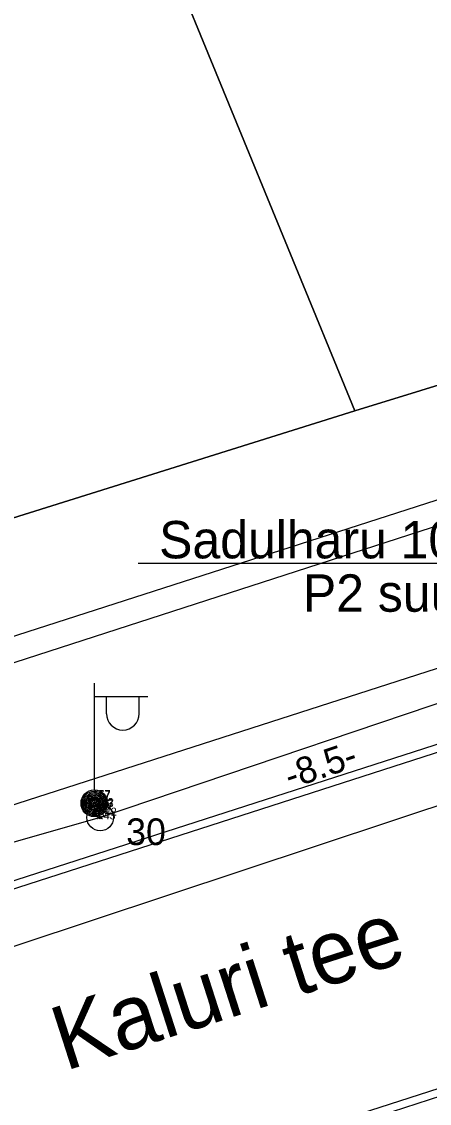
# Model space of a CAD drawing. Extents: x 546339 to 546593, y 6597108 to 6597251.
# Drawn here: x 546460.54 to 546468.19, y 6597179 to 6597199.27 of the extents above; entities that cross this region are included whole.
import ezdxf

# ---------------------------------------------------------------- set-up
doc = ezdxf.new("R2010")
doc.units = 0
for name, color, linetype in [('HOONE', 7, 'Continuous'), ('JOONSIDE', 7, 'Continuous'), ('KOORDPUNKT', 7, 'Continuous'), ('MOOTKORG-EH2000', 7, 'Continuous'), ('MOOTMPUNKT', 7, 'Continuous'), ('MOOTNR', 7, 'Continuous'), ('MOOTPIIR', 7, 'Continuous'), ('PIIR', 7, 'Continuous'), ('POST', 7, 'Continuous'), ('SITRASS', 7, 'Continuous'), ('TEE', 7, 'Continuous')]:
    doc.layers.add(name, color=color, linetype=linetype)

msp = doc.modelspace()

# ---------------------------------------------------------------- linework, layer by layer
at = {"layer": 'HOONE'}
for points in [[(546461.888, 6597184.636), (546461.9, 6597184.561)], [(546461.916, 6597184.6), (546461.899, 6597184.649)]]:
    msp.add_lwpolyline(points, dxfattribs=at)
at = {"layer": 'KOORDPUNKT'}
for radius in [0.25, 0.025, 0.0221, 0.0191, 0.0161, 0.0132, 0.0102, 0.00726, 0.0043]:
    msp.add_circle((546462.018, 6597184.359), radius, dxfattribs=at)
at = {"layer": 'MOOTMPUNKT'}
for centre in [(546461.875, 6597184.723), (546461.879, 6597184.706), (546461.913, 6597184.474), (546461.936, 6597184.543)]:
    msp.add_circle(centre, 0.03, dxfattribs=at)
at = {"layer": 'MOOTPIIR'}
for points in [[(546431.038, 6597182.742), (546435.363, 6597179.169), (546476.861, 6597192.584), (546477.551, 6597196.157), (546480.466, 6597197.411), (546483.506, 6597194.527), (546510.21, 6597203.146)], [(546510.398, 6597198.602), (546490.433, 6597192.051), (546491.122, 6597184.372), (546487.988, 6597183.494), (546485.449, 6597190.17), (546474.636, 6597186.911), (546476.297, 6597179.326), (546473.131, 6597178.291), (546470.279, 6597185.218), (546447.869, 6597177.79), (546448.872, 6597171.02), (546446.584, 6597170.142), (546443.888, 6597176.348), (546374.62, 6597155.63)]]:
    msp.add_lwpolyline(points, dxfattribs=at)
at = {"layer": 'PIIR'}
for points in [[(546459.55, 6597209.598), (546466.79, 6597191.98), (546491.04, 6597199.45), (546483.698, 6597217.73)], [(546424.887, 6597197.926), (546431.99, 6597181.07), (546466.79, 6597191.98), (546459.55, 6597209.598)], [(546510.07, 6597205.36), (546491.04, 6597199.45), (546466.79, 6597191.98), (546431.99, 6597181.07), (546399.93, 6597171.7), (546399.49, 6597172.55), (546362.07, 6597160.42), (546350.54, 6597167.22), (546341.457, 6597167.537)]]:
    msp.add_lwpolyline(points, dxfattribs=at)
at = {"layer": 'POST'}
for p, q in [((546461.907, 6597184.875), (546461.907, 6597186.875)), ((546461.907, 6597186.625), (546462.907, 6597186.625)), ((546462.134, 6597186.304), (546462.134, 6597186.625)), ((546462.747, 6597186.304), (546462.747, 6597186.625)), ((546461.907, 6597184.625), (546461.907, 6597184.625))]:
    msp.add_line(p, q, dxfattribs=at)
for radius in [0.25, 0.225, 0.2, 0.175, 0.15, 0.125, 0.1, 0.075, 0.05, 0.025]:
    msp.add_circle((546461.907, 6597184.625), radius, dxfattribs=at)
msp.add_arc((546462.441, 6597186.304), 0.306, 180, 0, dxfattribs=at)
at = {"layer": 'SITRASS'}
for points in [[(546472.601, 6597187.97), (546470.63, 6597189.117), (546462.729, 6597189.117)], [(546472.601, 6597187.97), (546470.118, 6597187.092), (546462.018, 6597184.359), (546455.281, 6597182.437), (546447.986, 6597180.224), (546445.217, 6597179.513)]]:
    msp.add_lwpolyline(points, dxfattribs=at)
at = {"layer": 'TEE'}
for p, q in [((546518.272, 6597195.197), (546396.577, 6597156.011)), ((546439.027, 6597176.299), (546484.965, 6597191.091)), ((546484.87, 6597190.902), (546439.237, 6597176.208))]:
    msp.add_line(p, q, dxfattribs=at)
for points in [[(546514.456, 6597205.157), (546396.804, 6597167.285), (546396.804, 6597167.285)], [(546515.375, 6597202.301), (546397.724, 6597164.429), (546397.724, 6597164.429)], [(546396.531, 6597156.154), (546518.226, 6597195.34), (546518.226, 6597195.34)]]:
    msp.add_lwpolyline(points, dxfattribs=at)

# ---------------------------------------------------------------- texts
at = {"layer": 'JOONSIDE'}
msp.add_text('-8.5-', height=0.5, rotation=18.6456, dxfattribs=at).set_placement((546465.572, 6597184.887))
at = {"layer": 'KOORDPUNKT'}
msp.add_text('30', height=0.5, dxfattribs=at).set_placement((546462.504, 6597183.842))
at = {"layer": 'MOOTKORG-EH2000'}
for s, p in [('7.42', (546461.875, 6597184.573)), ('7.43', (546461.879, 6597184.556)), ('7.43', (546461.913, 6597184.324)), ('7.42', (546461.936, 6597184.393))]:
    msp.add_text(s, height=0.15, dxfattribs=at).set_placement(p)
at = {"layer": 'MOOTNR'}
for p in [(546461.875, 6597184.723), (546461.879, 6597184.706), (546461.913, 6597184.474), (546461.936, 6597184.543)]:
    msp.add_text('157', height=0.15, dxfattribs=at).set_placement(p)
at = {"layer": 'SITRASS'}
for s, p in [('Sadulharu 100/50', (546463.121, 6597189.215)), ('P2 suund 2', (546465.816, 6597188.215))]:
    msp.add_text(s, height=0.7, dxfattribs=at).set_placement(p)
at = {"layer": 'TEE'}
msp.add_text('Kaluri tee', height=1.2, rotation=17.8487, dxfattribs=at).set_placement((546461.358, 6597179.605))

doc.saveas('drawing.dxf')
